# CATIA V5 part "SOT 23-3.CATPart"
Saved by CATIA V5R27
Part number: SOT 23-3
Definition: SOT 23-3
Nomenclature: SOT 23-3 v1
Source: Unknown
Bounding box of the stored display mesh (mm): x -1.52 to 1.52, y -0.1 to 0.94, z -1.32 to 1.32
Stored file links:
  E:\university\my-thesis\My Thesis Publication\Final-Updata\CAD\SOT 23-3.CATPart
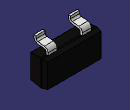
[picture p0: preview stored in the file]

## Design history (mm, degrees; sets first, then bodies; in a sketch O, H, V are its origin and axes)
Body1 "Body1" (main body)
  Solid1: solid without history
